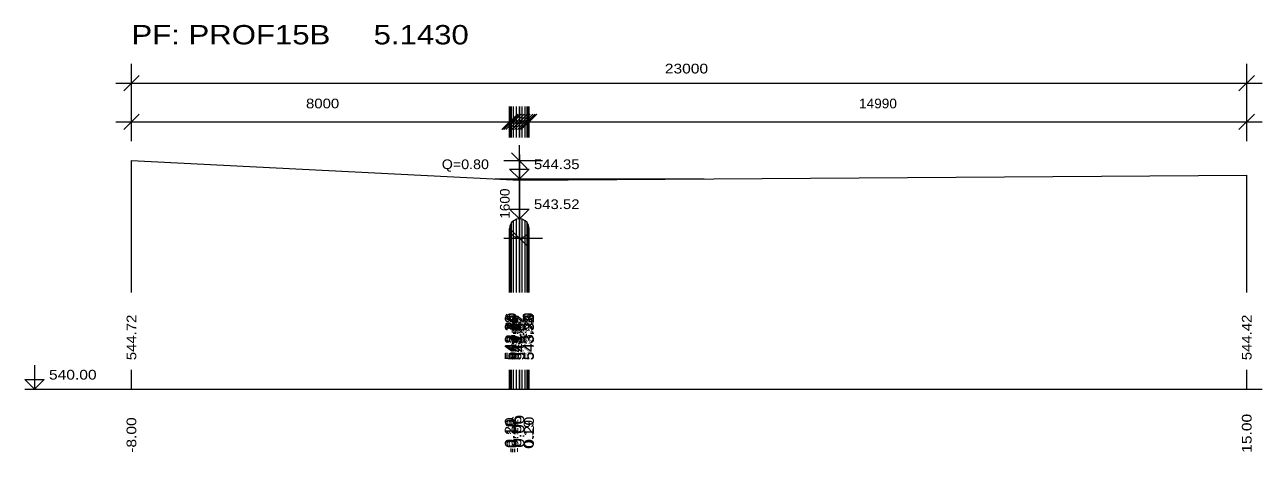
# Model space of a CAD drawing. Extents: x 7 to 442, y -393 to 441.
# Drawn here: x 411.84 to 437.36, y -353.33 to -344.51 of the extents above; entities that cross this region are included whole.
import ezdxf

# ---------------------------------------------------------------- set-up
doc = ezdxf.new("R2010")
doc.units = 0
doc.header["$LTSCALE"] = 0.08
doc.layers.add('7', color=7, linetype='Continuous', lineweight=13)

msp = doc.modelspace()

# ---------------------------------------------------------------- linework, layer by layer
at = {"layer": '7'}
for p, q in [((414.038, -346.914), (414.038, -345.314)), ((437.038, -346.914), (437.038, -345.314)), ((413.718, -345.714), (437.358, -345.714)), ((413.878, -345.874), (414.198, -345.554)), ((436.878, -345.874), (437.198, -345.554)), ((414.038, -346.834), (414.038, -346.194)), ((421.838, -346.834), (421.838, -346.194)), ((421.848, -346.834), (421.848, -346.194)), ((421.848, -346.834), (421.848, -346.194)), ((421.878, -346.834), (421.878, -346.194)), ((421.878, -346.834), (421.878, -346.194)), ((421.918, -346.834), (421.918, -346.194)), ((421.918, -346.834), (421.918, -346.194)), ((421.978, -346.834), (421.978, -346.194)), ((421.978, -346.834), (421.978, -346.194)), ((422.038, -346.834), (422.038, -346.194)), ((422.038, -346.834), (422.038, -346.194)), ((422.038, -346.834), (422.038, -346.194)), ((422.048, -346.834), (422.048, -346.194)), ((422.048, -346.834), (422.048, -346.194)), ((422.098, -346.834), (422.098, -346.194)), ((422.098, -346.834), (422.098, -346.194)), ((422.158, -346.834), (422.158, -346.194)), ((422.158, -346.834), (422.158, -346.194)), ((422.198, -346.834), (422.198, -346.194)), ((422.198, -346.834), (422.198, -346.194)), ((422.228, -346.834), (422.228, -346.194)), ((422.228, -346.834), (422.228, -346.194)), ((422.238, -346.834), (422.238, -346.194)), ((437.038, -346.834), (437.038, -346.194)), ((413.718, -346.514), (437.358, -346.514)), ((413.878, -346.674), (414.198, -346.354)), ((421.678, -346.674), (421.998, -346.354)), ((421.688, -346.674), (422.008, -346.354)), ((421.688, -346.674), (422.008, -346.354)), ((421.718, -346.674), (422.038, -346.354)), ((421.718, -346.674), (422.038, -346.354)), ((421.758, -346.674), (422.078, -346.354)), ((421.758, -346.674), (422.078, -346.354)), ((421.818, -346.674), (422.138, -346.354)), ((421.818, -346.674), (422.138, -346.354)), ((421.878, -346.674), (422.198, -346.354)), ((421.878, -346.674), (422.198, -346.354)), ((421.878, -346.674), (422.198, -346.354)), ((421.888, -346.674), (422.208, -346.354)), ((421.888, -346.674), (422.208, -346.354)), ((421.938, -346.674), (422.258, -346.354)), ((421.938, -346.674), (422.258, -346.354)), ((421.998, -346.674), (422.318, -346.354)), ((421.998, -346.674), (422.318, -346.354)), ((422.038, -346.674), (422.358, -346.354)), ((422.038, -346.674), (422.358, -346.354)), ((422.068, -346.674), (422.388, -346.354)), ((422.068, -346.674), (422.388, -346.354)), ((422.078, -346.674), (422.398, -346.354)), ((436.878, -346.674), (437.198, -346.354)), ((422.038, -349.074), (422.038, -346.994)), ((414.038, -350.034), (414.038, -347.314)), ((421.718, -347.314), (422.518, -347.314)), ((422.198, -347.474), (421.878, -347.154)), ((421.531, -347.689), (425.846, -347.689)), ((422.038, -350.034), (422.038, -347.714)), ((422.048, -350.034), (422.048, -347.714)), ((437.038, -350.034), (437.038, -347.614)), ((421.878, -350.034), (421.878, -348.594)), ((421.918, -350.034), (421.918, -348.554)), ((421.978, -350.034), (421.978, -348.524)), ((422.038, -350.034), (422.038, -348.514)), ((422.038, -348.514), (422.048, -348.514)), ((422.048, -350.034), (422.048, -348.514)), ((422.098, -350.034), (422.098, -348.524)), ((422.158, -350.034), (422.158, -348.554)), ((422.198, -350.034), (422.198, -348.594)), ((421.838, -350.034), (421.838, -348.714)), ((421.848, -350.034), (421.848, -348.654)), ((421.848, -350.034), (421.848, -348.774)), ((422.198, -349.074), (421.878, -348.754)), ((421.878, -350.034), (421.878, -348.834)), ((422.198, -350.034), (422.198, -348.834)), ((422.228, -350.034), (422.228, -348.654)), ((422.228, -350.034), (422.228, -348.774)), ((422.238, -350.034), (422.238, -348.714)), ((421.718, -348.914), (422.518, -348.914)), ((421.918, -350.034), (421.918, -348.874)), ((421.978, -350.034), (421.978, -348.904)), ((422.038, -350.034), (422.038, -348.914)), ((422.098, -350.034), (422.098, -348.904)), ((422.158, -350.034), (422.158, -348.874)), ((414.038, -352.034), (414.038, -351.634)), ((421.838, -352.034), (421.838, -351.634)), ((421.848, -352.034), (421.848, -351.634)), ((421.848, -352.034), (421.848, -351.634)), ((421.878, -352.034), (421.878, -351.634)), ((421.878, -352.034), (421.878, -351.634)), ((421.918, -352.034), (421.918, -351.634)), ((421.918, -352.034), (421.918, -351.634)), ((421.978, -352.034), (421.978, -351.634)), ((421.978, -352.034), (421.978, -351.634)), ((422.038, -352.034), (422.038, -351.634)), ((422.038, -352.034), (422.038, -351.634)), ((422.038, -352.034), (422.038, -351.634)), ((422.048, -352.034), (422.048, -351.634)), ((422.048, -352.034), (422.048, -351.634)), ((422.098, -352.034), (422.098, -351.634)), ((422.098, -352.034), (422.098, -351.634)), ((422.158, -352.034), (422.158, -351.634)), ((422.158, -352.034), (422.158, -351.634)), ((422.198, -352.034), (422.198, -351.634)), ((422.198, -352.034), (422.198, -351.634)), ((422.228, -352.034), (422.228, -351.634)), ((422.228, -352.034), (422.228, -351.634)), ((422.238, -352.034), (422.238, -351.634)), ((437.038, -352.034), (437.038, -351.634)), ((411.838, -352.034), (437.358, -352.034))]:
    msp.add_line(p, q, dxfattribs=at)
for points in [[(414.038, -347.314), (422.038, -347.714), (422.038, -348.514), (421.978, -348.524), (421.918, -348.554), (421.878, -348.594), (421.848, -348.654), (421.838, -348.714), (421.848, -348.774), (421.878, -348.834), (421.918, -348.874), (421.978, -348.904), (422.038, -348.914), (422.098, -348.904), (422.158, -348.874), (422.198, -348.834), (422.228, -348.774), (422.238, -348.714), (422.228, -348.654), (422.198, -348.594), (422.158, -348.554), (422.098, -348.524), (422.048, -348.514), (422.048, -347.714), (437.038, -347.614)], [(422.038, -347.189), (422.038, -347.689), (421.838, -347.489), (422.238, -347.489), (422.038, -347.689)], [(422.038, -348.014), (422.038, -348.514), (421.838, -348.314), (422.238, -348.314), (422.038, -348.514)], [(412.038, -351.534), (412.038, -352.034), (411.838, -351.834), (412.238, -351.834), (412.038, -352.034)]]:
    msp.add_lwpolyline(points, dxfattribs=at)

# ---------------------------------------------------------------- texts
for s, height, width, p in [('PF: PROF15B     5.1430', 0.4, 1.2, (414.038, -344.914)), ('23000', 0.2, 1.2, (425.038, -345.514)), ('8000', 0.2, 1.15, (417.638, -346.234)), ('14990', 0.2, 1.05, (429.043, -346.234)), ('Q=0.80', 0.2, 1.1, (420.438, -347.489)), ('544.35', 0.2, 1.15, (422.338, -347.489)), ('543.52', 0.2, 1.15, (422.338, -348.314)), ('540.00', 0.2, 1.2, (412.338, -351.834))]:
    msp.add_text(s, height=height, dxfattribs=dict(at, width=width)).set_placement(p)
for s, width, p in [('1600', 1.05, (421.838, -348.514)), ('544.72 ', 1.15, (414.138, -351.434)), ('543.32 ', 1.15, (421.938, -351.434)), ('543.26 ', 1.2, (421.948, -351.434)), ('543.38 ', 1.15, (421.948, -351.434)), ('543.20 ', 1.2, (421.978, -351.434)), ('543.44 ', 1.15, (421.978, -351.434)), ('543.48 ', 1.15, (422.018, -351.434)), ('543.16 ', 1.15, (422.018, -351.434)), ('543.13 ', 1.1, (422.078, -351.434)), ('543.51 ', 1.05, (422.078, -351.434)), ('544.32 ', 1.15, (422.138, -351.434)), ('543.52 ', 1.15, (422.138, -351.434)), ('543.12 ', 1.1, (422.138, -351.434)), ('543.52 ', 1.15, (422.148, -351.434)), ('544.32 ', 1.15, (422.148, -351.434)), ('543.13 ', 1.1, (422.198, -351.434)), ('543.51 ', 1.05, (422.198, -351.434)), ('543.16 ', 1.15, (422.258, -351.434)), ('543.48 ', 1.15, (422.258, -351.434)), ('543.20 ', 1.2, (422.298, -351.434)), ('543.44 ', 1.15, (422.298, -351.434)), ('543.26 ', 1.2, (422.328, -351.434)), ('543.38 ', 1.15, (422.328, -351.434)), ('543.32 ', 1.15, (422.338, -351.434)), ('544.42 ', 1.15, (437.138, -351.434)), (' -8.00 ', 1.2, (414.138, -353.434)), (' -0.20 ', 1.2, (421.938, -353.434)), (' -0.19 ', 1.15, (421.948, -353.434)), (' -0.19 ', 1.15, (421.948, -353.434)), (' -0.16 ', 1.15, (421.978, -353.434)), (' -0.16 ', 1.15, (421.978, -353.434)), (' -0.12 ', 1.15, (422.018, -353.434)), (' -0.12 ', 1.15, (422.018, -353.434)), (' -0.06 ', 1.25, (422.078, -353.434)), (' -0.06 ', 1.25, (422.078, -353.434)), ('  0.00 ', 1.3, (422.138, -353.434)), ('  0.00 ', 1.3, (422.138, -353.434)), ('  0.00 ', 1.3, (422.138, -353.434)), ('  0.01 ', 1.15, (422.148, -353.434)), ('  0.01 ', 1.15, (422.148, -353.434)), ('  0.06 ', 1.25, (422.198, -353.434)), ('  0.06 ', 1.25, (422.198, -353.434)), ('  0.12 ', 1.15, (422.258, -353.434)), ('  0.12 ', 1.15, (422.258, -353.434)), ('  0.16 ', 1.2, (422.298, -353.434)), ('  0.16 ', 1.2, (422.298, -353.434)), ('  0.19 ', 1.15, (422.328, -353.434)), ('  0.19 ', 1.15, (422.328, -353.434)), ('  0.20 ', 1.25, (422.338, -353.434)), (' 15.00 ', 1.2, (437.138, -353.434))]:
    msp.add_text(s, height=0.2, rotation=90, dxfattribs=dict(at, width=width)).set_placement(p)

doc.saveas('drawing.dxf')
